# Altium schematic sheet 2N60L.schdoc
size 127 x 101 mm
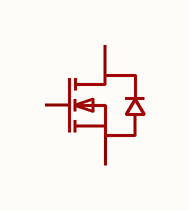
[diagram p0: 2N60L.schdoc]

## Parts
Q?  2n60l  [TO-252-3_L6.6-W6.1-P4.56-LS9.9-BL-CW]  (value not drawn)

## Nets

Not connected (* = marked no-connect by the designer): Q? 1(G) 2(D) 3(S)

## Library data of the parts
Q? = 2n60l: 数量:1个N沟道;漏源电压(Vdss):600V;连续漏极电流(Id):2A;导通电阻(RDS(on)):4.2Ω@10V;耗散功率(Pd):45W;阈值电压(Vgs(th)):4V;; Manufacturer: UMW(友台半导体); AddInBom: yes; ModelId: c043866d099b42aab5996239b2d192e7; ModelTransform: 259.842,389.763,0,0,0,0,0,41.34,0; Number: 1个N沟道; Drain to Source Voltage: 600V; Current - Continuous Drain(Id): 2A; Pd - Power Dissipation: 45W; Gate Threshold Voltage (Vgs(th)): 4V; Gate Charge(Qg): 7.2nC@10V; Input Capacitance(Ciss): 320pF; Type: N沟道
